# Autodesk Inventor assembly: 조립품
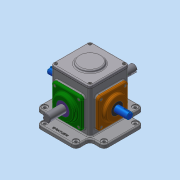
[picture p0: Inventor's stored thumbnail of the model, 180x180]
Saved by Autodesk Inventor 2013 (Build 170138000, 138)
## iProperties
Created: 2019-12
Part Number: 조립품
Document SubType Name: Assembly
Designer: dgall
Author: dgall
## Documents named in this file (16)
- C:\Users\dgall\Desktop\391204V1045\조립품.iam
- C:\Users\dgall\Desktop\391204V1045\개스킷.ipt
- C:\Users\dgall\Desktop\391204V1045\메인베벨기어.ipt
- C:\Users\dgall\Desktop\391204V1045\메인축.ipt
- C:\Users\dgall\Desktop\391204V1045\메인커버.ipt
- C:\Users\dgall\Desktop\391204V1045\베어링 6203.ipt
- C:\Users\dgall\Desktop\391204V1045\베어링 6204.ipt
- C:\Users\dgall\Desktop\391204V1045\본체.ipt
- C:\Users\dgall\Desktop\391204V1045\볼트 M4.ipt
- C:\Users\dgall\Desktop\391204V1045\상부커버.ipt
- C:\Users\dgall\Desktop\391204V1045\서브베벨기어.ipt
- C:\Users\dgall\Desktop\391204V1045\서브축.ipt
- C:\Users\dgall\Desktop\391204V1045\서브커버.ipt
- C:\Users\dgall\Desktop\391204V1045\오일 실 17 32 8.ipt
- C:\Users\dgall\Desktop\391204V1045\오일 실 20 35 8.ipt
- C:\Users\dgall\Desktop\391204V1045\키 4x4.ipt
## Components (1 placed, 1 different names)
1. 개스킷:1
